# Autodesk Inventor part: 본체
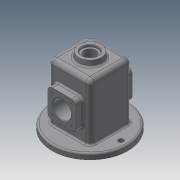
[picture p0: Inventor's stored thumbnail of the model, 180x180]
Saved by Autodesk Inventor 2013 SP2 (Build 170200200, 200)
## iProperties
Created: 2021-08
Part Number: 본체
Material: Generic
Document SubType Name: Modeling
Designer: kumco
Density: 1 g/cm^3
Mass: 304.335 g
Surface Area: 949.017 cm^2
Volume: 304.335 cm^3
Author: kumco
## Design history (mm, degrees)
sketch "스케치1"
  geometry: L1 (-37, -37)-(37, -37); L2 (37, -37)-(37, 37); L3 (37, 37)-(-37, 37); L4 (-37, 37)-(-37, -37); L5 (-37, -37)-(37, 37); L6 (37, -37)-(-37, 37); 1 further point
  constraints: 12 end point, 2 midpoint, 2 parallel, 1 horizontal, 1 perpendicular
  dimensions: "d0" = 74 distance of L3.end L2.end; "d1" = 74 distance of L2.end L1.end
extrude "돌출1" new body sketch "스케치1" distance "d2" = 110; taper "d3" = 0 deg
fillet "모깎기1" dims "d4" = 8
fillet "모깎기2" dims "d5" = 8
feature "쉘1" dims "d6" = 5
sketch "스케치2"
  geometry: L1 (29, -37)-(-29, -37) reference; L2 (37, 29)-(37, -29) reference; L3 (-29, 37)-(29, 37) reference; L4 (-37, -29)-(-37, 29) reference; C1 r 67 at (0, 0); A1 r 8 centre (-29, -29) between (-37, -29) and (-29, -37) reference; A2 r 8 centre (29, -29) between (29, -37) and (37, -29) reference; A3 r 8 centre (29, 29) between (37, 29) and (29, 37) reference; A4 r 8 centre (-29, 29) between (-29, 37) and (-37, 29) reference; 1 further point
  constraints: 1 centre point, 1 coincident
  dimensions: "d7" = 134 diameter of C1
extrude "돌출2" join sketch "스케치2" distance "d9" = 10; taper "d10" = 0 deg
sketch "스케치3"
  geometry: L1 (58, 0)-(58, 102) reference; L2 (29, 0)-(29, 55); C1 r 25 at (29, 55)
  constraints: 2 end point, 1 centre point, 1 coincident, 1 parallel
  dimensions: "d11" = 55 distance of L2.start L2.end; "d12" = 50 diameter of C1
extrude "돌출3" join sketch "스케치3" distance "d13" = 7; taper "d14" = -20 deg
sketch "스케치4"
  geometry: L1 (0, -92)-(0, 0) reference; L2 (29, -102)-(29, -47); L3 (54, -72)-(4, -72); L4 (4, -72)-(4, -22); L5 (4, -22)-(54, -22); L6 (54, -22)-(54, -72); L7 (54, -72)-(4, -22); L8 (4, -72)-(54, -22)
  constraints: 14 end point, 3 parallel, 2 midpoint, 1 horizontal, 1 perpendicular
  dimensions: "d15" = 55 distance of L2.start L2.end; "d16" = 50 distance of L4.end L5.end; "d17" = 50 distance of L3.end L4.end
extrude "돌출4" join sketch "스케치4" distance "d18" = 13; taper "d19" = 0 deg
sketch "스케치5"
  geometry: C1 r 22.452 at (29, -47) reference; C2 r 16 at (29, -47); 1 further point
  constraints: 1 centre point, 1 coincident
  dimensions: "d20" = 32 diameter of C2
extrude "돌출5" cut sketch "스케치5" stored distance "d21" = 13; taper "d22" = 0 deg
sketch "스케치6"
  geometry: L1 (46, -64)-(12, -64); L2 (12, -64)-(12, -30); L3 (12, -30)-(46, -30); L4 (46, -30)-(46, -64); L5 (46, -64)-(12, -30); L6 (12, -64)-(46, -30); C1 r 16 at (29, -47) reference; 5 further points
  constraints: 12 end point, 4 coincident, 2 midpoint, 2 parallel, 1 horizontal, 1 perpendicular
  dimensions: "d23" = 34 distance of L2.end L3.end; "d24" = 34 distance of L1.end L2.end
hole "구멍1" sketch "스케치6" at (12, -30), (46, -30), (46, -64), (12, -64) diameter "d25" = 3.242; stored, may be unused: countersink angle "d29" = 90 deg, drill point angle "d31" = 118 deg; dims "d26" = 8, "d27" = 4, "d28" = 2, "d30" = 10
sketch "스케치7"
  geometry: C1 r 67 at (0, 0) reference; A1 r 55 centre (0, 0) between (0, 55) and (0, -55)
  constraints: 2 point on circle, 1 centre point, 1 coincident
  dimensions: "d32" = 110 diameter of A1
hole "구멍2" sketch "스케치7" at (0, 55), (0, -55) diameter "d33" = 9; stored, may be unused: countersink angle "d37" = 90 deg, drill point angle "d39" = 118 deg; dims "d34" = 8, "d35" = 4, "d36" = 2, "d38" = 10
node "작업 평면1"
sketch "스케치8"
  geometry: C1 r 20 at (0, 0); 1 further point
  constraints: 1 centre point, 1 coincident
  dimensions: "d41" = 40 diameter of C1
extrude "돌출6" join sketch "스케치8" stored distance "d42" = 40 (= d41); taper "d43" = 6 deg
sketch "스케치9"
  geometry: C1 r 20 at (0, 0) reference; C2 r 14 at (0, 0)
  constraints: 1 centre point, 1 coincident
  dimensions: "d44" = 28 diameter of C2
extrude "돌출7" cut sketch "스케치9" distance "d45" = 4; taper "d46" = 0 deg
sketch "스케치10"
  geometry: C1 r 14 at (0, 0) reference; C2 r 10.5 at (0, 0)
  constraints: 1 centre point, 1 coincident
  dimensions: "d47" = 21 diameter of C2
extrude "돌출8" cut sketch "스케치10" stored distance "d48" = 4; taper "d49" = 0 deg
sketch "스케치11"
  geometry: L1 (-8, 0)-(-8, -92) reference; L2 (9, 18)-(49, 18) reference; 2 further points
  constraints: 1 other
  dimensions: "d50" = 37 distance from line of point (29, -10) L1; "d51" = 28 distance from line of point (29, -10) L2
feature "엠보싱1" sketch "스케치11" dims "d0" = 74, "d1" = 74, "d52" = 0.5, "d53" = 0
fillet "모깎기3" dims "d54" = 8
fillet "모깎기4" dims "d55" = 3
fillet "모깎기5" dims "d56" = 3
chamfer "모따기1" distance "d57" = 1; stored, may be unused: second distance "d58" = 2, angle "d59" = 45 deg
fillet "모깎기6" dims "d60" = 3
node "솔리드1"
mirror "대칭1"
mirror "대칭2"
